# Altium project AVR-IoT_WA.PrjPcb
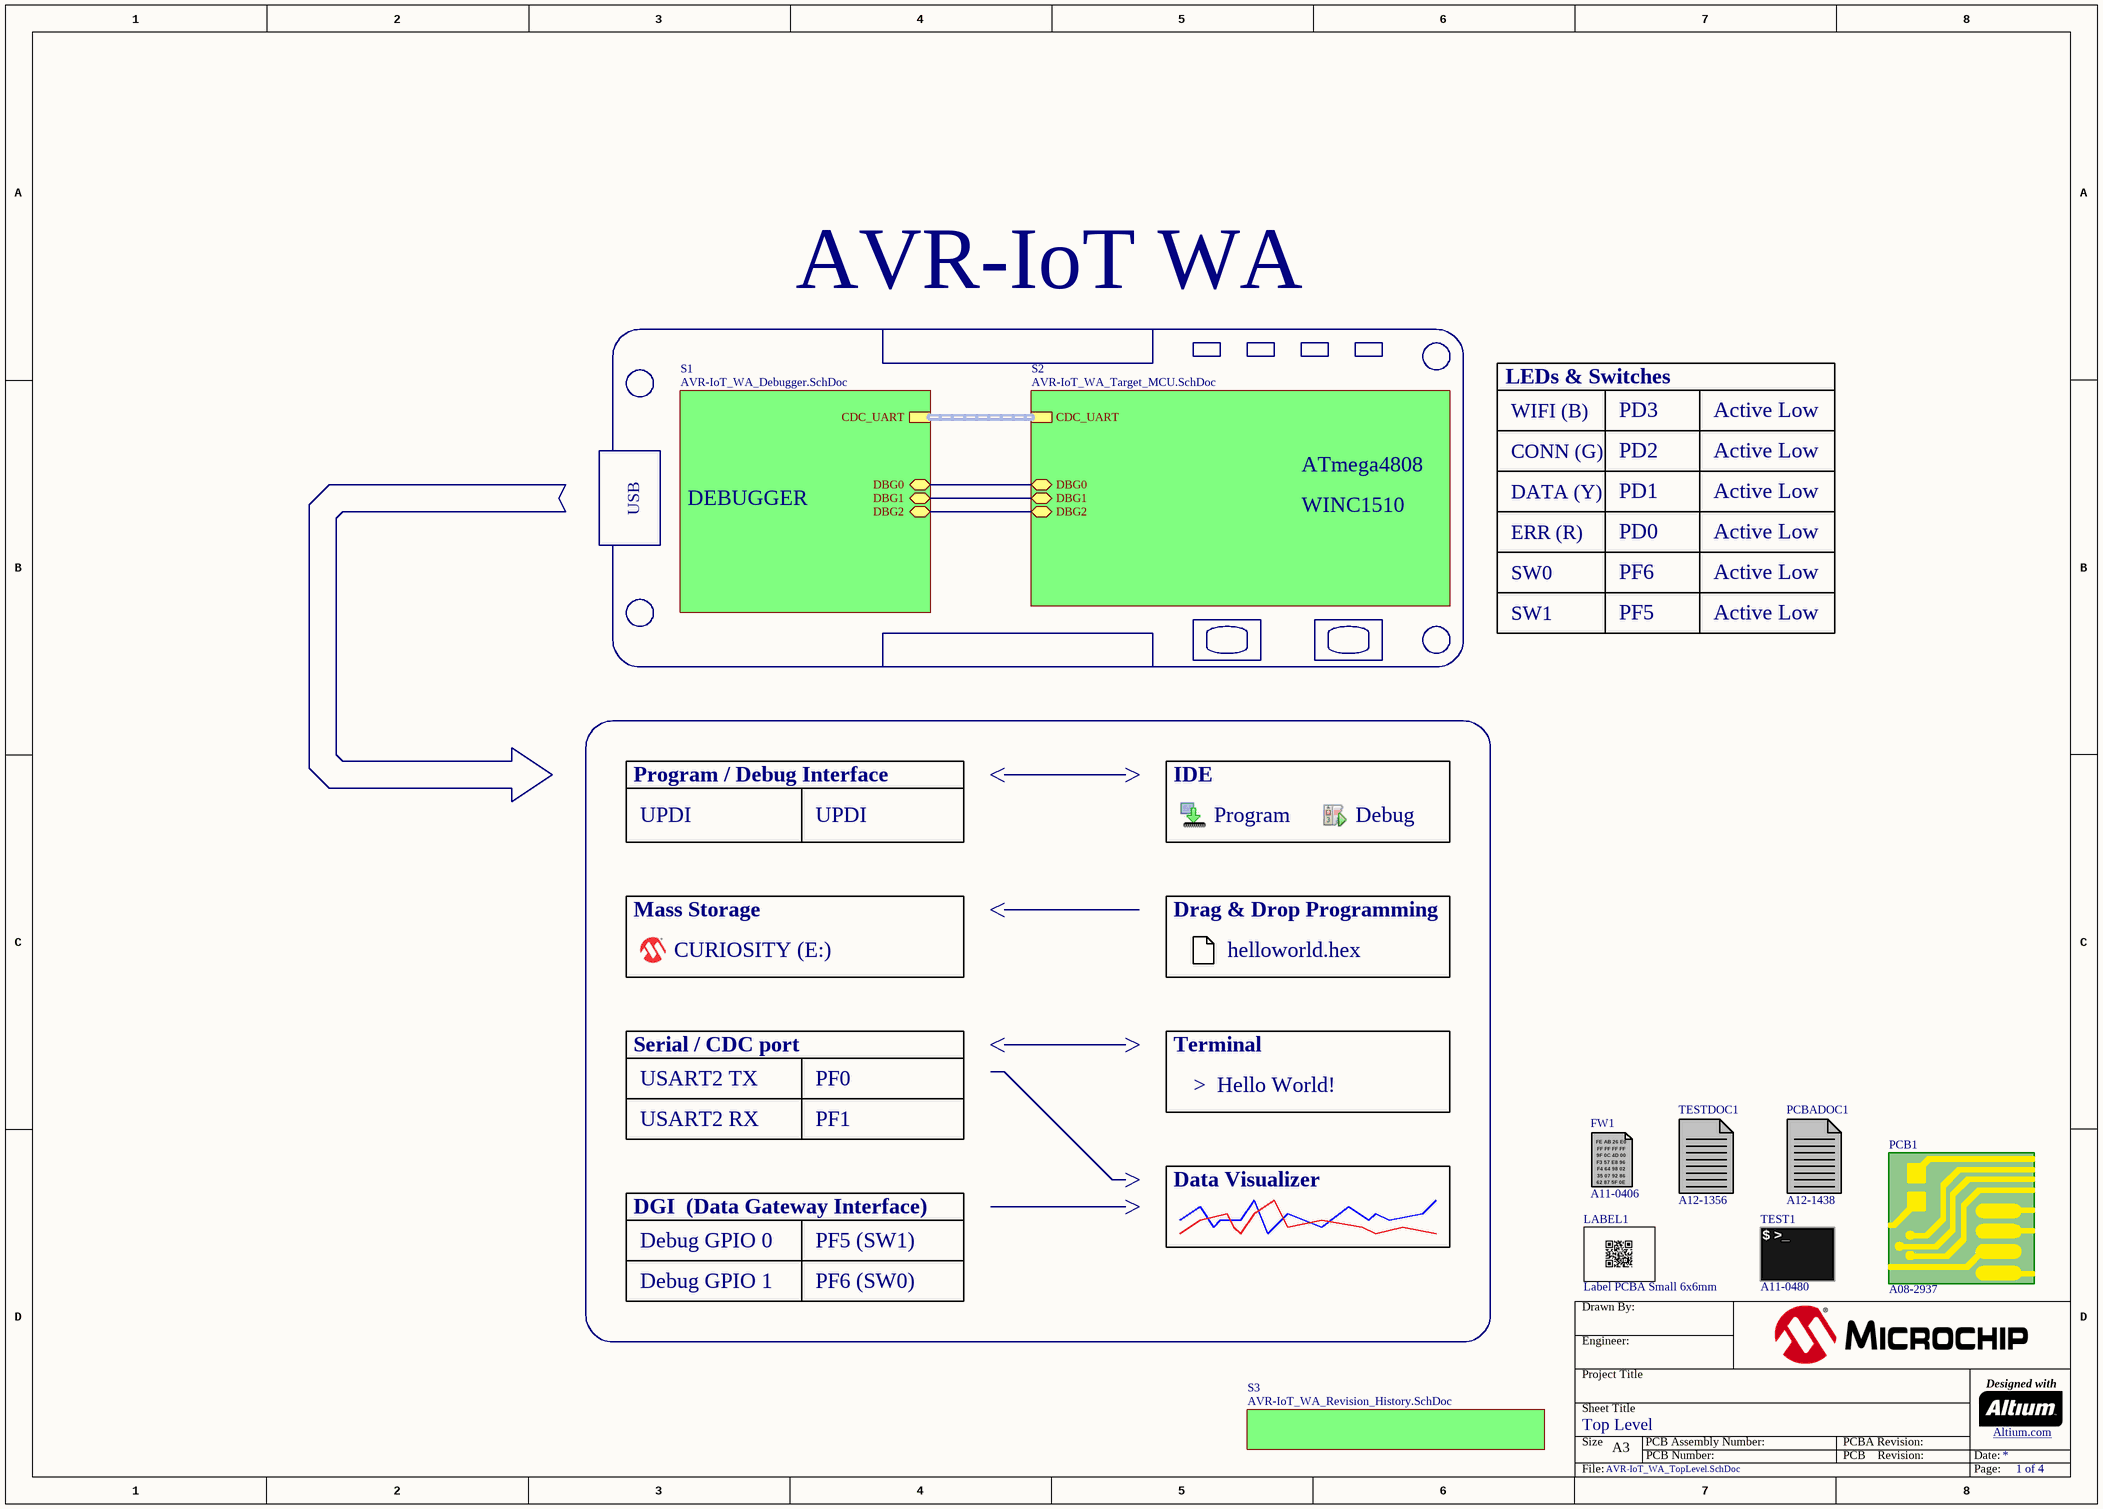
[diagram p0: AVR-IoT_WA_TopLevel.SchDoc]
Target_Name: ATmega4808; Project_Title: AVR-IoT WA; Project_Engineer: TF; Project_Drawn_By: TF; PCB_rev: 5; PCBA_rev: 1; Organization_1: Microchip Norway; AN_PCBA: A09-3349; AN_PCB: A08-2937; Address_3: Norway; Address_2: 7069 Trondheim; Address_1: Brøsetvegen 164
4 sheets, 86 parts. Net scope: hierarchical (ports join the sheet entries above them; power ports are global).
Board file: AVR-IoT_WA.PcbDoc
Sheets:
  AVR-IoT_WA_TopLevel.SchDoc
    S2 = AVR-IoT_WA_Target_MCU.SchDoc
    S1 = AVR-IoT_WA_Debugger.SchDoc
    S3 = AVR-IoT_WA_Revision_History.SchDoc

## Sheet AVR-IoT_WA_TopLevel.SchDoc: Top Level
size A3; Organization: Microchip Norway; Address1: Brøsetvegen 164; Address2: 7069 Trondheim; Address3: Norway; DocumentNumber: A09-3349; Revision: 1; SheetNumber: 1; SheetTotal: 4; DrawnBy: TF; Engineer: TF; PageSetup: Record=PageOptions¦CenterHorizontal=True¦CenterVertical=True¦PrintScale=1.01¦XCorrection=1.00¦YCorrection=1.00¦PrintKind=1¦BorderSize=5000000¦LeftOffset=0¦BottomOffset=0¦Orientation=2¦PaperLength=1000¦PaperWidth=1000¦Scale=100¦PaperSource=7¦PrintQuality=-4¦MediaType=1¦DitherType=10¦PaperKind=A3 (297 x 420 mm)¦PrintScaleMode=1; ProjectTitle: AVR-IoT WA; PCBNumber: A08-2937; PCBRevision: 5

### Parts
FW1  AN: A11-0406  (mechanical)
LABEL1  value Label PCBA Small 6x6mm  [AP9-00049]
PCB1  AN: A08-2937  (mechanical)
PCBADOC1  AN: A12-1438  (mechanical)
TEST1  AN: A11-0480  (mechanical)
TESTDOC1  AN: A12-1356  (hidden comment: Use test fixture A13-0177)  (mechanical)

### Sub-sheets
S1 = AVR-IoT_WA_Debugger.SchDoc: CDC_UART (harness UART), DBG2 (bidir), DBG1 (bidir), DBG0 (bidir)
S2 = AVR-IoT_WA_Target_MCU.SchDoc: DBG0 (bidir), CDC_UART (harness UART), DBG1 (bidir), DBG2 (bidir)
S3 = AVR-IoT_WA_Revision_History.SchDoc: no entries

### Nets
PF5_SW1_DGI: sheet S2/DBG2, sheet S1/DBG2
PF6_SW0_DGI: sheet S2/DBG1, sheet S1/DBG1
UPDI: sheet S2/DBG0, sheet S1/DBG0

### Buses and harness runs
harness sheet S1/CDC_UART = sheet S2/CDC_UART

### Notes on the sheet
- LEDs & Switches
- WIFI (B)
- PD3
- Active Low
- USB
- DEBUGGER
- WINC1510
- CONN (G)
- DATA (Y)
- PD2
- PD1
- SW0
- ERR (R)
- PF6
- PD0
- SW1
- PF5
- Program / Debug Interface
- IDE
- UPDI
- Program
- Debug
- Mass Storage
- Drag & Drop Programming
- CURIOSITY (E:)
- helloworld.hex
- Serial / CDC port
- Terminal
- USART2 TX
- USART2 RX
- PF1
- PF0
- >  Hello World!
- Data Visualizer
- DGI  (Data Gateway Interface)
- Debug GPIO 0
- PF5 (SW1)
- Debug GPIO 1
- PF6 (SW0)

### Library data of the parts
FW1 = A11-0406: nEDBG firmware; PartGroup: Software,Firmware,Tools; Value: debugger firmware
LABEL1 = A09-0612: PCBA identification label PP Top White Gloss; PartGroup: Mechanical devices,Packaging materials,Printed Labels,PCBA; Manufacturer: ACT Logimark AS; MPN: 505462
PCB1 = A08-2937: AVR-IoT Wx PCB documentation; PartGroup: Mechanical devices,Printed circuit boards
PCBADOC1 = A12-1438: AVR-IoT WA PCBA documentation; PartGroup: Documentation,PCBA Documents,Atmel; Value: A09-3349 AVR-IoT WA PCBA documentation
TEST1 = A11-0480: Fixture test for AVR-IoT WA test; PartGroup: Software,Test software,Starter Kit
TESTDOC1 = A12-1356: AVR-IoT Wx Test Instructions; PartGroup: Documentation,Procedures,Test Instructions

## Sheet AVR-IoT_WA_Target_MCU.SchDoc: Target MCU
size A3; Organization: Microchip Norway; Address1: Brøsetvegen 164; Address2: 7069 Trondheim; Address3: Norway; DocumentNumber: A09-3349; Revision: 1; SheetNumber: 2; SheetTotal: 4; DrawnBy: TF; Engineer: TF; PageSetup: Record=PageOptions¦CenterHorizontal=True¦CenterVertical=True¦PrintScale=1.01¦XCorrection=1.00¦YCorrection=1.00¦PrintKind=1¦BorderSize=5000000¦LeftOffset=0¦BottomOffset=0¦Orientation=2¦PaperLength=1000¦PaperWidth=1000¦Scale=100¦PaperSource=7¦PrintQuality=-4¦MediaType=1¦DitherType=10¦PaperKind=A3 (297 x 420 mm)¦PrintScaleMode=1; ProjectTitle: AVR-IoT WA; PCBNumber: A08-2937; PCBRevision: 5
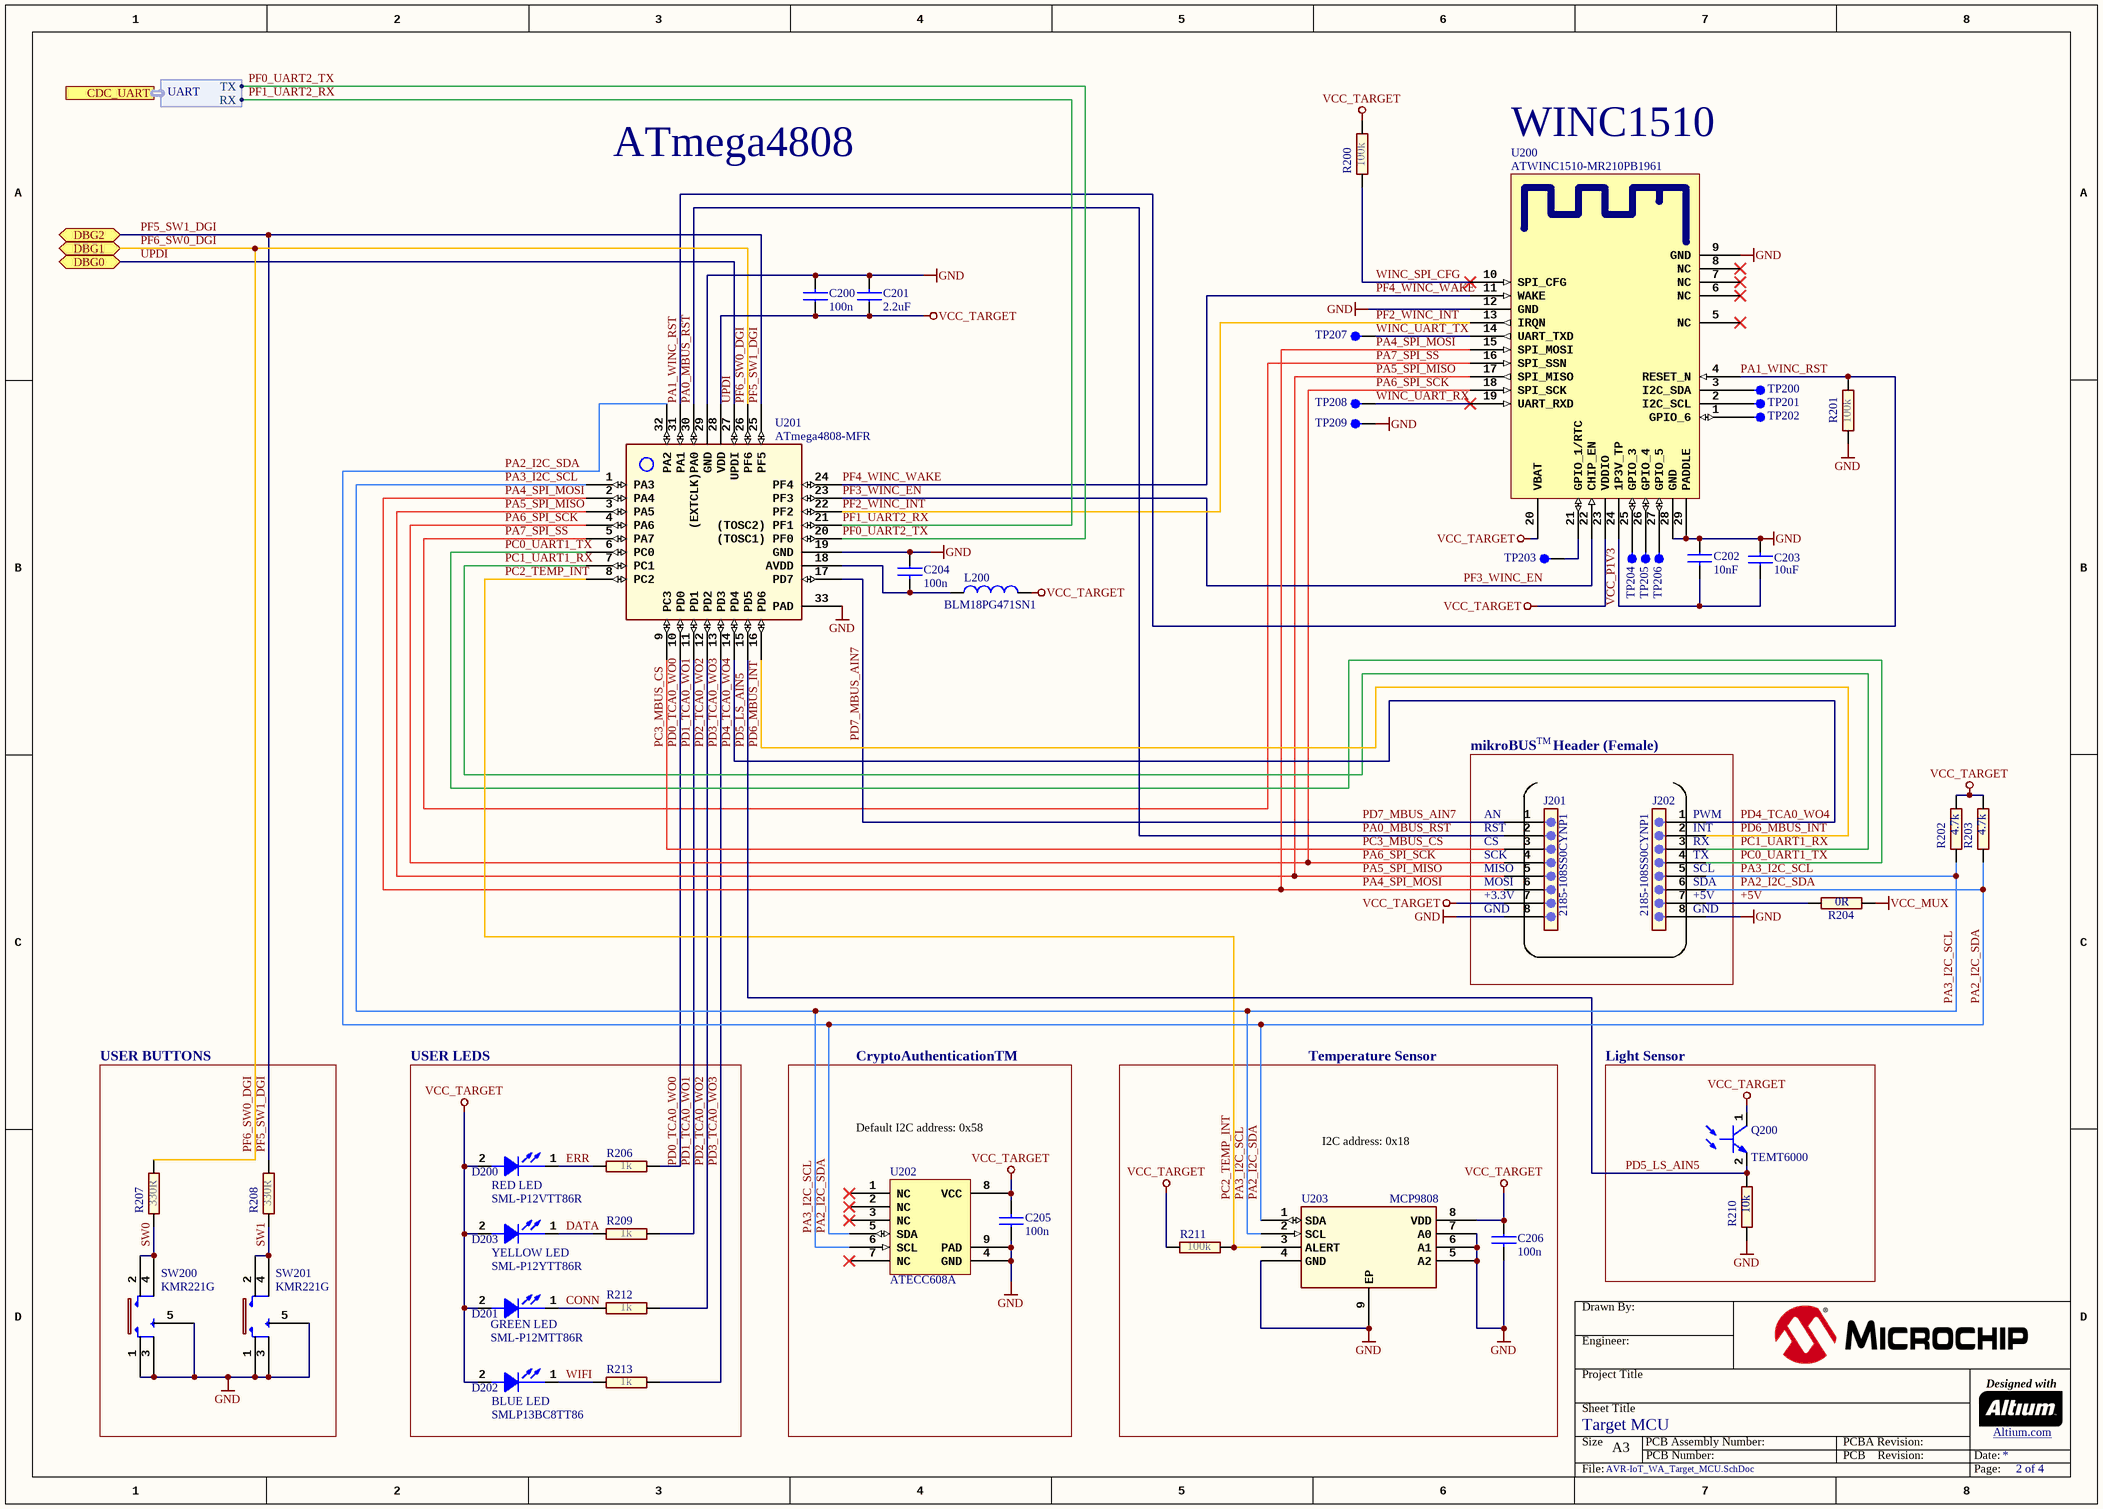
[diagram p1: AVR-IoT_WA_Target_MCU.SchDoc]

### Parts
C200  value 100n  [AP1-00053]
C201  value 2.2uF  [AP1-00053]
C202  value 10nF  [AP1-00053]
C203  value 10uF  [AP1-00053]
C204  value 100n  [AP1-00053]
C205  value 100n  [AP1-00053]
C206  value 100n  [AP1-00053]
D200  value RED LED  MPN: SML-P12VTT86R  [AP4-00160]
D201  value GREEN LED  MPN: SML-P12MTT86R  [AP4-00160]
D202  value BLUE LED  MPN: SMLP13BC8TT86  [AP4-00160]
D203  value YELLOW LED  MPN: SML-P12YTT86R  [AP4-00160]
J201  MPN: 2185-108SS0CYNP1  [AP8-01081]
J202  MPN: 2185-108SS0CYNP1  [AP8-01081]
L200  value BLM18PG471SN1  [AP3-00005]
Q200  value TEMT6000  [AP9-00011]
R200  value 100k  [AP2-00011]
R201  value 100k  [AP2-00011]
R202  value 4.7k  [AP2-00011]
R203  value 4.7k  [AP2-00011]
R204  value 0R  [AP2-00000]
R206  value 1k  [AP2-00011]
R207  value 330R  [AP2-00011]
R208  value 330R  [AP2-00011]
R209  value 1k  [AP2-00011]
R210  value 10k  [AP2-00011]
R211  value 100k  [AP2-00011]
R212  value 1k  [AP2-00011]
R213  value 1k  [AP2-00011]
SW200  value KMR221G  [AP8-00274]
SW201  value KMR221G  [AP8-00274]
TP200  (no value)  [AP8-01149]  (no BOM)
TP201  (no value)  [AP8-01149]  (no BOM)
TP202  (no value)  [AP8-01149]  (no BOM)
TP203  (no value)  [AP8-01149]  (no BOM)
TP204  (no value)  [AP8-01149]  (no BOM)
TP205  (no value)  [AP8-01149]  (no BOM)
TP206  (no value)  [AP8-01149]  (no BOM)
TP207  (no value)  [AP8-01149]  (no BOM)
TP208  (no value)  [AP8-01149]  (no BOM)
TP209  (no value)  [AP8-01149]  (no BOM)
U200  value ATWINC1510-MR210PB1961  [AP9-00127]  (hidden comment: Firmware version 19.6.1)
U201  value ATmega4808-MFR  [AP6-00418]
U202  (no value)  [AP6-00409]
U203  value MCP9808  [AP6-00519]

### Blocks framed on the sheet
USER BUTTONS: R207 R208 SW200 SW201
USER LEDS: D200-D203 R206 R209 R212 R213
CryptoAuthenticationTM: C205 U202
Temperature Sensor: C206 R211 U203
Light Sensor: Q200 R210

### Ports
CDC_UART (harness UART), DBG0 (bidir), DBG1 (bidir), DBG2 (bidir)

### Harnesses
UART: TX, RX

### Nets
GND: C200.2 C201.2 C202.1 C203.2 C204.1 C205.1 C206.2 J201.8 J202.8 R201.2 R210.2 SW200.1 SW200.3 SW200.5(GND) SW201.1 SW201.3 SW201.5(GND) TP209.1 U200.9(GND) U200.12(GND) U200.28(GND) U200.29(PADDLE) U201.19(GND) U201.29(GND) U201.33(PAD) U202.4(GND) U202.9(PAD) U203.4(GND) U203.5(A2) U203.6(A1) U203.7(A0) U203.9(EP)
VCC_MUX: R204.2
VCC_TARGET: C200.1 C201.1 C205.2 C206.1 D200.2(ANODE) D201.2(ANODE) D202.2(ANODE) D203.2(ANODE) J201.7 L200.2 Q200.1(C) R200.2 R202.1 R203.2 R211.1 U200.20(VBAT) U200.23(VDDIO) U201.28(VDD) U202.8(VCC) U203.8(VDD)
+5V: J202.7 R204.1
CONN: D201.1(CATHODE) R212.2
DATA: D203.1(CATHODE) R209.2
ERR: D200.1(CATHODE) R206.2
PA0_MBUS_RST: J201.2 U201.30((EXTCLK)PA0)
PA1_WINC_RST: R201.1 U200.4(RESET_N) U201.31(PA1)
PA2_I2C_SDA: J202.6 R203.1 U201.32(PA2) U202.5(SDA) U203.1(SDA)
PA3_I2C_SCL: J202.5 R202.2 U201.1(PA3) U202.6(SCL) U203.2(SCL)
PA4_SPI_MOSI: J201.6 U200.15(SPI_MOSI) U201.2(PA4)
PA5_SPI_MISO: J201.5 U200.17(SPI_MISO) U201.3(PA5)
PA6_SPI_SCK: J201.4 U200.18(SPI_SCK) U201.4(PA6)
PA7_SPI_SS: U200.16(SPI_SSN) U201.5(PA7)
PC0_UART1_TX: J202.4 U201.6(PC0)
PC1_UART1_RX: J202.3 U201.7(PC1)
PC2_TEMP_INT: R211.2 U201.8(PC2) U203.3(ALERT)
PC3_MBUS_CS: J201.3 U201.9(PC3)
PD0_TCA0_WO0: R206.1 U201.10(PD0)
PD1_TCA0_WO1: R209.1 U201.11(PD1)
PD2_TCA0_WO2: R212.1 U201.12(PD2)
PD3_TCA0_WO3: R213.1 U201.13(PD3)
PD4_TCA0_WO4: J202.1 U201.14(PD4)
PD5_LS_AIN5: Q200.2(E) R210.1 U201.15(PD5)
PD6_MBUS_INT: J202.2 U201.16(PD6)
PD7_MBUS_AIN7: J201.1 U201.17(PD7)
PF0_UART2_TX: U201.20((TOSC1)_PF0) ; port CDC_UART.TX
PF1_UART2_RX: U201.21((TOSC2)_PF1) ; port CDC_UART.RX
PF2_WINC_INT: U200.13(IRQN) U201.22(PF2)
PF3_WINC_EN: U200.22(CHIP_EN) U201.23(PF3)
PF4_WINC_WAKE: U200.11(WAKE) U201.24(PF4)
PF5_SW1_DGI: R208.1 U201.25(PF5) ; port DBG2
PF6_SW0_DGI: R207.1 U201.26(PF6) ; port DBG1
SW0: R207.2 SW200.2 SW200.4
SW1: R208.2 SW201.2 SW201.4
UPDI: U201.27(UPDI) ; port DBG0
VCC_P1V3: C202.2 C203.1 U200.24(1P3V_TP)
WIFI: D202.1(CATHODE) R213.2
WINC_SPI_CFG: R200.1 U200.10(SPI_CFG)
WINC_UART_RX: TP208.1 U200.19(UART_RXD)
WINC_UART_TX: TP207.1 U200.14(UART_TXD)
NetC204_2: C204.2 L200.1 U201.18(AVDD)
NetTP200_1: TP200.1 U200.3(I2C_SDA)
NetTP201_1: TP201.1 U200.2(I2C_SCL)
NetTP202_1: TP202.1 U200.1(GPIO_6)
NetTP203_1: TP203.1 U200.21(GPIO_1/RTC)
NetTP204_1: TP204.1 U200.25(GPIO_3)
NetTP205_1: TP205.1 U200.26(GPIO_4)
NetTP206_1: TP206.1 U200.27(GPIO_5)

Not connected (* = marked no-connect by the designer): Q200 3; U200 5(NC)* 6(NC)* 7(NC)* 8(NC)*; U202 1(NC)* 2(NC)* 3(NC)* 7(NC)*

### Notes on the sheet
- WINC1510
- mikroBUS
- TM
- Header (Female)
- (near J201) AN
- (near J201) RST
- (near J201) CS
- (near J201) SCK
- (near J202) PWM
- (near J202) INT
- (near J202) RX
- (near J202) TX
- (near J201) MISO
- (near J201) MOSI
- (near J201) +3.3V
- (near J201) GND
- (near J202) SCL
- (near J202) SDA
- (near J202) +5V
- (near J202) GND
- Default I2C address: 0x58
- I2C address: 0x18
- (near U202) ATECC608A

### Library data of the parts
C200 C204-C206 = A01-0246: Ceramic capacitor, SMD 0402, X7R, 16V, +/-10%; Manufacturer: Kemet; MPN: C0402C104K4RACTU; PartGroup: Capacitors,Ceramic,SMD 0402; TemperatureRange: -55 - +125 deg C
C201 = A01-0493: CAP CER 2.2UF 10V 10% X5R 0402; PartGroup: Capacitors,Ceramic,SMD 0402; Manufacturer: tdk; MPN: C1005X5R1A225K; Tolerance: +/-10%; TemperatureRange: -55 to 85C
C202 = A01-0636: Ceramic capacitor, SMD 0402, X7R, 25V, 10%; PartGroup: Capacitors,Ceramic,SMD 0402; Manufacturer: Murata; MPN: GRM155R71E103KA01D; TemperatureRange: -55 to +125deg C
C203 = A01-0778: Ceramic capacitor, SMD 0402, X5R, 6.3V, 20%; PartGroup: Capacitors,Ceramic,SMD 0402; Manufacturer: Murata; MPN: GRM155R60J106ME15; Tolerance: +/-20%; TemperatureRange: -55 to 85 Deg.C
D200 = A10-0220: LED, SMD 0402, Red, Wave length=630nm, 2.1mcd @ (1mA, 1.7Vf)rohm; PartGroup: Opto,LEDs,SMD; TemperatureRange: -40 to +85
D201 = A10-0213: LED, SMD 0402, Green, Wave length=569nm, 2.1mcd @ (1mA, 1.9Vf)rohm; PartGroup: Opto,LEDs,SMD; TemperatureRange: -40 to +85
D202 = A10-0219: LED, SMD 0402, Blue, Wave length=470nm, 25mcd @ (5mA, 2.9Vf)rohm; PartGroup: Opto,LEDs,SMD; TemperatureRange: -40Â°C to +85Â°C
D203 = A10-0215: LED, SMD 0402, Yellow, Wave length=586nm, 7.6mcd @ (1mA, 1.9Vf); PartGroup: Opto,LEDs,SMD; Manufacturer: ROHM; TemperatureRange: -40 to +85
J201 J202 = A08-2791: 1x8 receptacle pin header, 2.54mm pitch THM, PIP; PartGroup: Mechanical devices,Connectors,Pin header receptacle; Manufacturer: WCON; Value: 2185-108SS0CYNP1
L200 = A03-0035: SMD RF inductor 0603. Z=470Ohm (@100MHz), Max R(dc)=0.20Ohm, Max current=1A; PartGroup: Inductors,EMI; Manufacturer: Murata; TemperatureRange: -55
Q200 = A10-0025: light sensor; PartGroup: Opto; Manufacturer: vishay; MPN: TEMT6000X01
R200 R201 R211 = A02-0260: Thick film resistor, SMD 0402, 1/16W, 1%; PartGroup: Resistors,SMD,0402 1%; Manufacturer: ASJ Holdings; MPN: CR10-1003-FK; TemperatureRange: -55ï¿½ to +125ï¿½C
R202 R203 = A02-1016: Thick film resistror, SMD 0402, 1/16W, 1%; PartGroup: Resistors,SMD,0402 1%; Manufacturer: Yageo; MPN: RC0402FR-074K7L; TemperatureRange: -55 to +155 deg C
R204 = A02-0163: RES 0.0 OHM 1/16W 0402 SMD; PartGroup: Resistors,SMD,0402 1%; Manufacturer: (n/a); MPN: RMCF0402ZT0R00; Tolerance: 1 %; TemperatureRange: -55 - +125 deg C
R206 R209 R212 R213 = A02-0212: Thick film resistor, SMD 0402, 1/16W, 1%; PartGroup: Resistors,SMD,0402 1%; Manufacturer: ASJ Holdings; MPN: CR10-1001-FK; TemperatureRange: -55 - +125 deg C
R207 R208 = A02-0882: Thick film resistor, SMD 0402, 1/16W, 1%; Manufacturer: Yageo; MPN: RC0402FR-07330RL; PartGroup: Resistors,SMD,0402 1%; TemperatureRange: -55 to +155 deg C
R210 = A02-0835: Thick film resistror, SMD 0402, 1/16W, 1%; PartGroup: Resistors,SMD,0402 1%; Manufacturer: Yageo; MPN: RC0402FR-0710KL; TemperatureRange: â€“55 to +155 deg C
SW200 SW201 = A08-0420: Microminiature Tact Switch for SMT; PartGroup: Mechanical devices,Switches,SMD; Manufacturer: ITT Corporation
TP200-TP209 = A08-2933: SMD Single Testpad, 1mm, No-silk; PartGroup: Mechanical devices,Connectors,Test points
U200 = A06-1660: IEEE 802.11 b/g/n module, 8Mbit Flash Memory, with FEM, PCB Antenna, with Shield, with MAC, Firmware version 19.6.1; PartGroup: Integrated Circuits,Modules,Radio Module WiFi; Manufacturer: Microchip; TemperatureRange: -40Â°C to +85Â°C
U201 = A06-1639: Atmel 8-bit RISC MCU, 48K Flash, 32pin QFN; PartGroup: Integrated Circuits,MCU, MPU, DSP,AVR MCU; Manufacturer: Microchip; TemperatureRange: -40Â°C to +125Â°C
U202 = A06-1647: ATECC608A with an I2C Interface and a 8 Pin UDFN; Manufacturer: Microchip; MPN: ATECC608A-MAH1H-S; PartGroup: Integrated Circuits,Special function,Encryption; Value: ATECC608A I2C (Google Cloud)
U203 = A06-1645: Â±0.5Â°C Maximum Accuracy Digital Temperature Sensor, I2C/SMBus; PartGroup: Integrated Circuits,Sensors; Manufacturer: Microchip; MPN: MCP9808T-E/MC; TemperatureRange: -40Â°C to +125Â°C

## Sheet AVR-IoT_WA_Debugger.SchDoc: Debugger
size A3; Organization: Microchip Norway; Address1: Brøsetvegen 164; Address2: 7069 Trondheim; Address3: Norway; DocumentNumber: A09-3349; Revision: 1; SheetNumber: 3; SheetTotal: 4; DrawnBy: TF; Engineer: TF; PageSetup: Record=PageOptions¦CenterHorizontal=True¦CenterVertical=True¦PrintScale=1.01¦XCorrection=1.00¦YCorrection=1.00¦PrintKind=1¦BorderSize=5000000¦LeftOffset=0¦BottomOffset=0¦Orientation=2¦PaperLength=1000¦PaperWidth=1000¦Scale=100¦PaperSource=7¦PrintQuality=-4¦MediaType=1¦DitherType=10¦PaperKind=A3 (297 x 420 mm)¦PrintScaleMode=1; ProjectTitle: AVR-IoT WA; PCBNumber: A08-2937; PCBRevision: 5
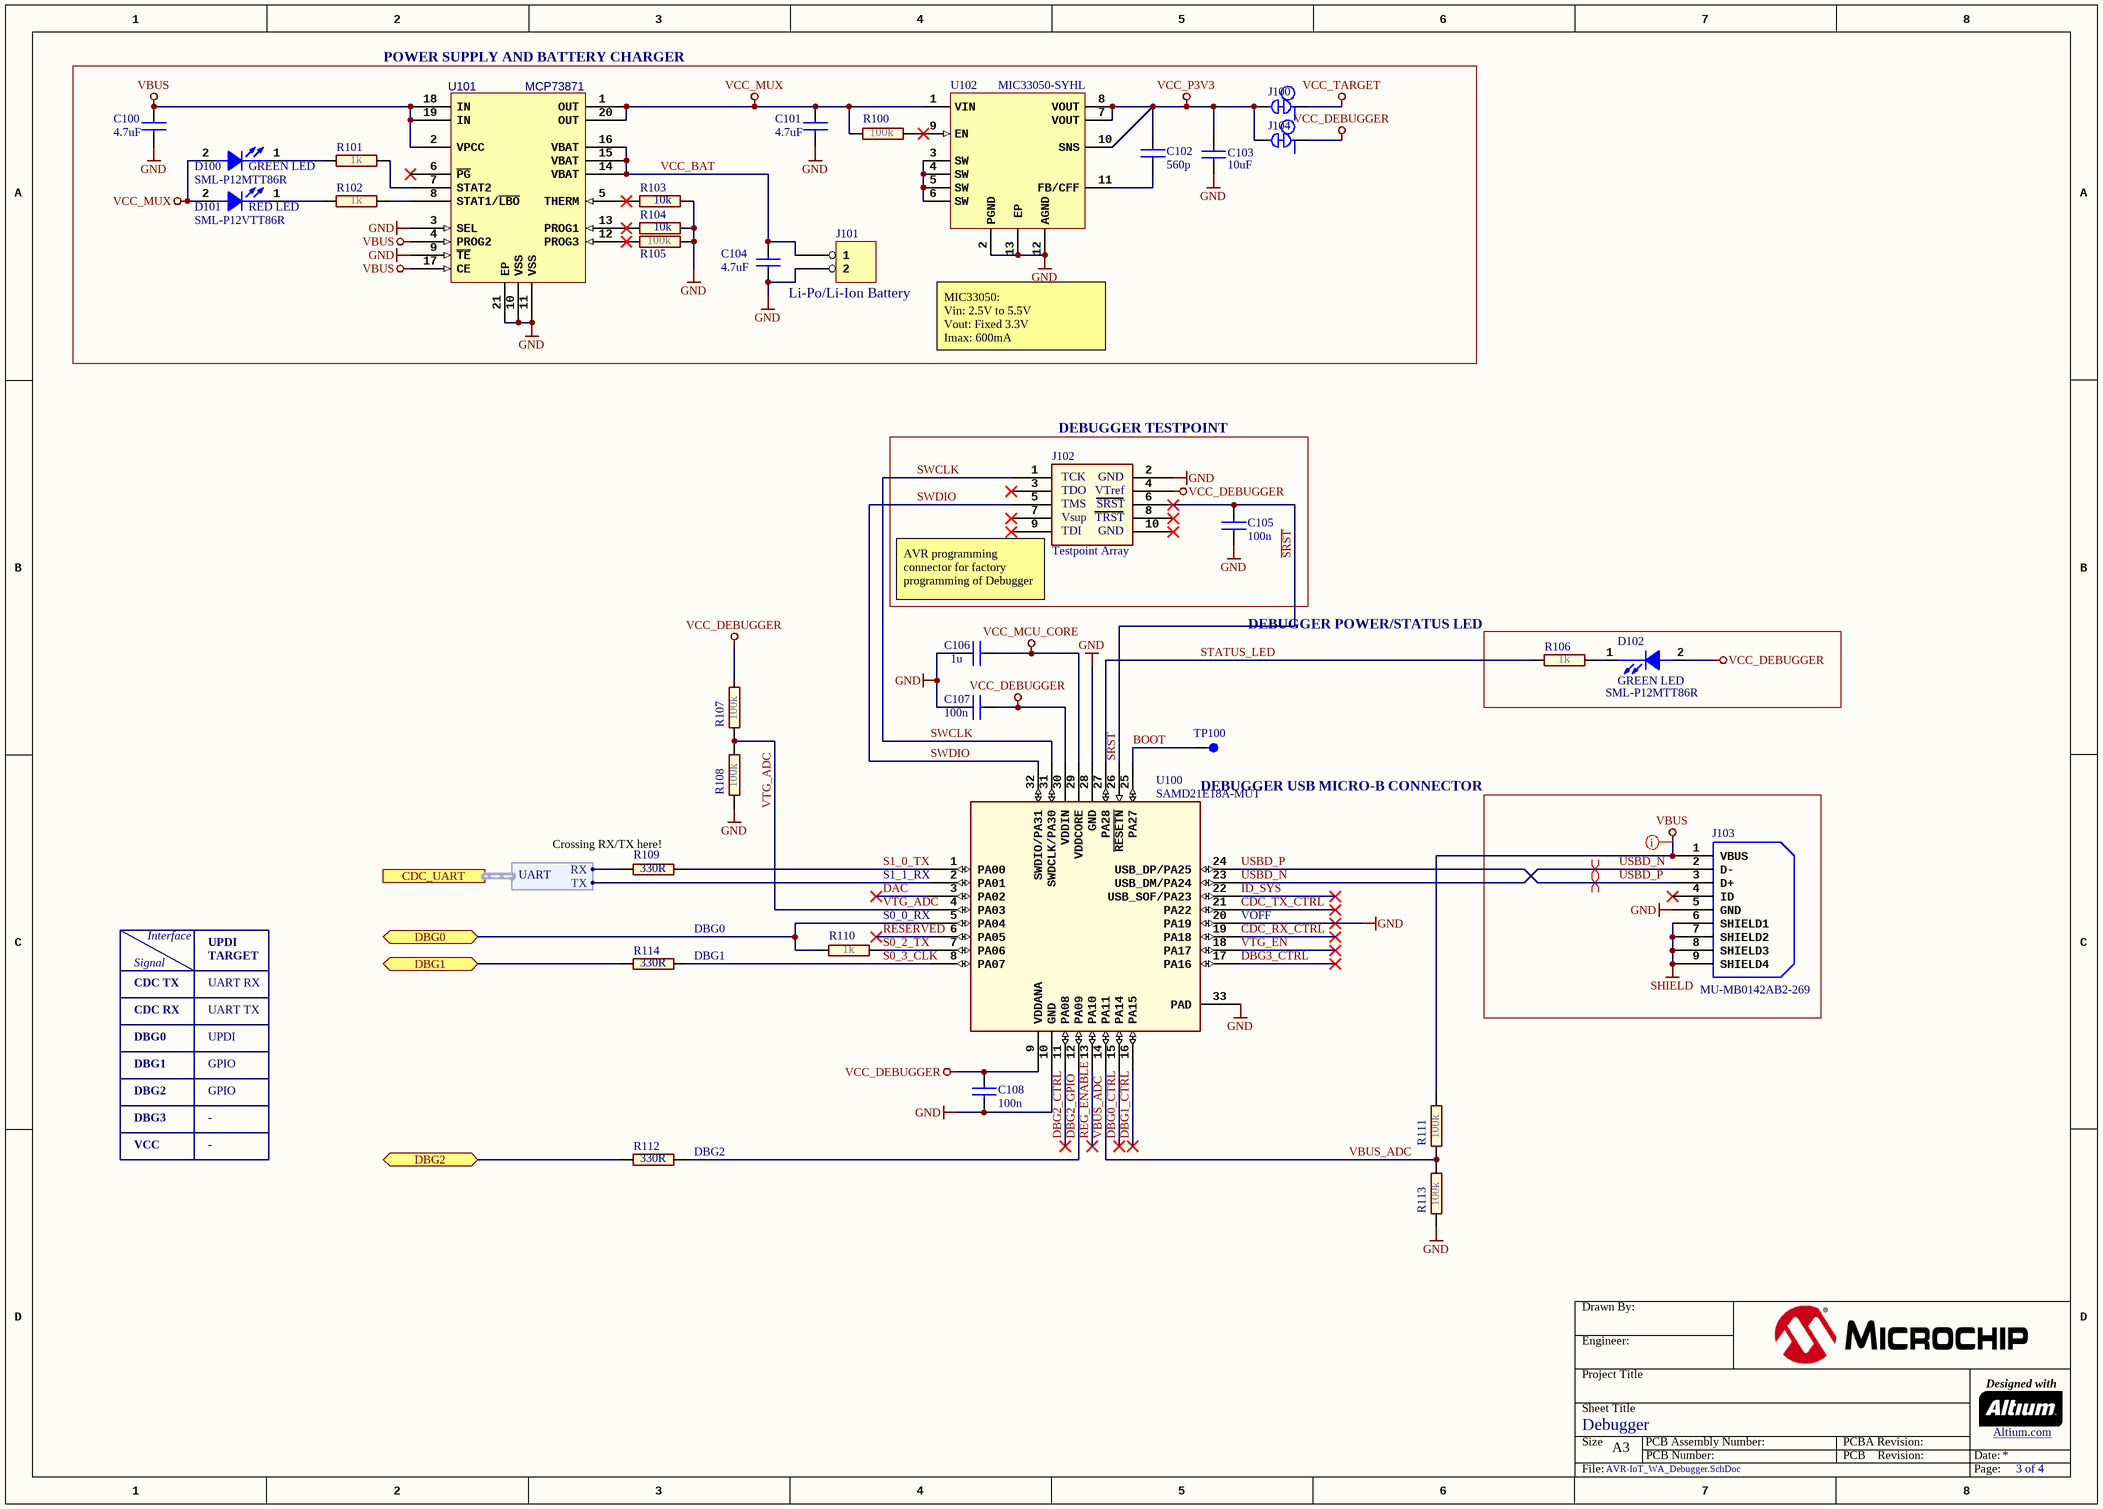
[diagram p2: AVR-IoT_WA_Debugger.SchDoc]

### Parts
C100  value 4.7uF  [AP1-00117]
C101  value 4.7uF  [AP1-00117]
C102  value 560p  [AP1-00053]
C103  value 10uF  [AP1-00053]
C104  value 4.7uF  [AP1-00117]
C105  value 100n  [AP1-00053]
C106  value 1u  [AP1-00053]
C107  value 100n  [AP1-00053]
C108  value 100n  [AP1-00053]
D100  value GREEN LED  MPN: SML-P12MTT86R  [AP4-00160]
D101  value RED LED  MPN: SML-P12VTT86R  [AP4-00160]
D102  value GREEN LED  MPN: SML-P12MTT86R  [AP4-00160]
J100  (no value)  [AP9-00044]  (net tie, no BOM)
J101  (no value)  [AP8-00831]
J102  value Testpoint Array  [AP8-00997]  (no BOM)
J103  value MU-MB0142AB2-269  [AP8-01099]
J104  (no value)  [AP9-00044]  (net tie, no BOM)
R100  value 100k  [AP2-00011]
R101  value 1k  [AP2-00011]
R102  value 1k  [AP2-00011]
R103  value 10k  [AP2-00011]
R104  value 10k  [AP2-00011]
R105  value 100k  [AP2-00011]
R106  value 1k  [AP2-00011]
R107  value 100k  [AP2-00011]
R108  value 100k  [AP2-00011]
R109  value 330R  [AP2-00011]
R110  value 1k  [AP2-00011]
R111  value 100k  [AP2-00011]
R112  value 330R  [AP2-00011]
R113  value 100k  [AP2-00011]
R114  value 330R  [AP2-00011]
TP100  PCB implemented component.  [AP8-00870]  (value not drawn)  (no BOM)
U100  value SAMD21E18A-MUT  [AP6-00418]  (hidden comment: QFN32)
U101  value MCP73871  [AP6-00165]
U102  value MIC33050-SYHL  [AP6-00528]

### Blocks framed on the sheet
DEBUGGER TESTPOINT: C105 J102
DEBUGGER POWER/STATUS LED: D102 R106
DEBUGGER USB MICRO-B CONNECTOR: J103

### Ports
CDC_UART (harness UART), DBG0 (bidir), DBG1 (bidir), DBG2 (bidir)

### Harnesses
UART: RX, TX

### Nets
GND: C100.2 C101.2 C103.1 C104.1 C105.1 C106.1 C107.1 C108.2 J101.2 J102.2 J103.5(GND) R103.2 R104.2 R105.2 R108.1 R113.2 U100.10(GND) U100.20(PA19) U100.28(GND) U100.33(PAD) U101.3(SEL) U101.9(~{TE}) U101.10(VSS) U101.11(VSS) U101.21(EP) U102.2(PGND) U102.12(AGND) U102.13(EP)
SHIELD: J103.6(SHIELD1) J103.7(SHIELD2) J103.8(SHIELD3) J103.9(SHIELD4)
VBUS: C100.1 J103.1(VBUS) R111.2 U101.2(VPCC) U101.4(PROG2) U101.17(CE) U101.18(IN) U101.19(IN)
VCC_DEBUGGER: C107.2 C108.1 D102.2(ANODE) J102.4 J104.1 R107.2 U100.9(VDDANA) U100.30(VDDIN)
VCC_MCU_CORE: C106.2 U100.29(VDDCORE)
VCC_MUX: C101.1 D100.2(ANODE) D101.2(ANODE) R100.1 U101.1(OUT) U101.20(OUT) U102.1(VIN)
VCC_P3V3: C102.1 C103.2 J100.2 J104.2 U102.7(VOUT) U102.8(VOUT) U102.10(SNS)
VCC_TARGET: J100.1
BOOT: TP100.1 U100.25(PA27)
CDC_RX_CTRL: U100.19(PA18)
CDC_TX_CTRL: U100.21(PA22)
DAC: U100.3(PA02)
DBG0_CTRL: U100.15(PA14)
DBG1_CTRL: U100.16(PA15)
DBG2_CTRL: U100.11(PA08)
DBG2_GPIO: R112.1 U100.12(PA09)
DBG3_CTRL: U100.17(PA16)
ID_SYS: U100.22(USB_SOF/PA23)
PF0_UART2_TX: U100.2(PA01) ; port CDC_UART.TX
PF1_UART2_RX: R109.1 ; port CDC_UART.RX
PF5_SW1_DGI: R112.2 ; port DBG2
PF6_SW0_DGI: R114.2 ; port DBG1
REG_ENABLE: U100.13(PA10)
RESERVED: U100.6(PA05)
S0_2_TX: R110.2 U100.7(PA06)
S0_3_CLK: R114.1 U100.8(PA07)
S1_0_TX: R109.2 U100.1(PA00)
~{SRST}: C105.2 J102.6 U100.26(~{RESETN})
STATUS_LED: R106.2 U100.27(PA28)
SWCLK: J102.1 U100.31(SWDCLK/PA30)
SWDIO: J102.5 U100.32(SWDIO/PA31)
UPDI: R110.1 U100.5(PA04) ; port DBG0
USBD_N: J103.2(D-) U100.23(USB_DM/PA24)
USBD_P: J103.3(D+) U100.24(USB_DP/PA25)
VBUS_ADC: R111.1 R113.1 U100.14(PA11)
VCC_BAT: C104.2 J101.1 U101.14(VBAT) U101.15(VBAT) U101.16(VBAT)
VTG_ADC: R107.1 R108.2 U100.4(PA03)
VTG_EN: U100.18(PA17)
NetC102_2: C102.2 U102.11(FB/CFF)
NetD100_1: D100.1(CATHODE) R101.2
NetD101_1: D101.1(CATHODE) R102.2
NetD102_1: D102.1(CATHODE) R106.1
NetR100_2: R100.2 U102.9(EN)
NetR101_1: R101.1 U101.7(STAT2)
NetR102_1: R102.1 U101.8(STAT1/~{LBO})
NetR103_1: R103.1 U101.5(THERM)
NetR104_1: R104.1 U101.13(PROG1)
NetR105_1: R105.1 U101.12(PROG3)
NetU102_3: U102.3(SW) U102.4(SW) U102.5(SW) U102.6(SW)

Not connected (* = marked no-connect by the designer): J102 3* 7* 8* 9* 10*; J103 4(ID)*; U101 6(~{PG})*

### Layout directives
differential pair: USBD_N, USBD_P
net class Power: VBUS

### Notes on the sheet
- POWER SUPPLY AND BATTERY CHARGER
- Li-Po/Li-Ion Battery
- MIC33050:
  Vin: 2.5V to 5.5V
  Vout: Fixed 3.3V
  Imax: 600mA
- (near J102) AVR programming connector for factory programming of Debugger
- (near R109) Crossing RX/TX here!
- S1_1_RX
- S0_0_RX
- (near U100) VOFF
- Signal
- CDC TX
- Interface
- UPDI
- UART RX
- TARGET
- (near R114) DBG0
- (near R114) DBG1
- DBG0
- CDC RX
- UART TX
- DBG1
- DBG2
- DBG3
- GPIO
- -
- VCC
- (near R112) DBG2

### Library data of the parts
C100 C101 C104 = A01-0377: Ceramic capacitor, SMD 0603, X5R, 10V, 10% (de31036); PartGroup: Capacitors,Ceramic,SMD 0603; Manufacturer: WALSIN Technology Corporation; MPN: 0603X475K100CT; TemperatureRange: -55 - +85 deg C
C102 = A01-0035: Ceramic capacitor, SMD 0402, X7R, 50V, +/-10%; PartGroup: Capacitors,Ceramic,SMD 0402; TemperatureRange: -55 - +125 deg C
C103 = A01-0778: as C203 on sheet AVR-IoT_WA_Target_MCU
C105 C107 C108 = A01-0246: Ceramic capacitor, SMD 0402, X7R, 16V, +/-10%; PartGroup: Capacitors,Ceramic,SMD 0402; Manufacturer: Kemet; MPN: C0402C104K4RACTU; TemperatureRange: -55 - +125 deg C
C106 = A01-0286: Ceramic capacitor, SMD 0402, X5R, 6.3V, +/-10% (de26942); PartGroup: Capacitors,Ceramic,SMD 0402; Manufacturer: Kemet; MPN: C0402C105K9PAC; TemperatureRange: -55 to 85 deg C
D100 D102 = A10-0213: as D201 on sheet AVR-IoT_WA_Target_MCU
D101 = A10-0220: as D200 on sheet AVR-IoT_WA_Target_MCU
J100 J104 = A09-0783: Default closed SMD strap, 0603 size; PartGroup: Mechanical devices,PCB implemented components; Value: SMD-STRAP_0603_CLOSED
J101 = A08-2071: Pin Header 1x2, 2mm THM, right entry, 100V AC/DC, 2A AC/DC (AWG #24)  (Element14:9491902); PartGroup: Mechanical devices,Connectors,Pin headers; Manufacturer: J.S.T. Mfg. Co. Ltd.; Value: S2B-PH-K-S; TemperatureRange: -25Â°C to +85Â°C
J102 = A08-2568: 10-pin Testpoint Array, 0.8mm Pad, 1.27mm Pitch; PartGroup: Mechanical devices,PCB implemented components,PCB plane connectors
J103 = A08-2839: USB micro AB, Surface mount signals and DIP shield; PartGroup: Mechanical devices,Connectors,USB; Manufacturer: Allen Creations Corp.; TemperatureRange: -30Â°C to +80Â°C
R100 R105 = A02-0260: as R200 on sheet AVR-IoT_WA_Target_MCU
R101 R102 R106 R110 = A02-0212: as R206 on sheet AVR-IoT_WA_Target_MCU
R103 R104 = A02-0835: as R210 on sheet AVR-IoT_WA_Target_MCU
R107 R108 R111 R113 = A02-0260: Thick film resistor, SMD 0402, 1/16W, 1%; Manufacturer: ASJ Holdings; MPN: CR10-1003-FK; PartGroup: Resistors,SMD,0402 1%; TemperatureRange: -55ï¿½ to +125ï¿½C
R109 R112 R114 = A02-0882: Thick film resistor, SMD 0402, 1/16W, 1%; PartGroup: Resistors,SMD,0402 1%; Manufacturer: Yageo; MPN: RC0402FR-07330RL; TemperatureRange: -55 to +155 deg C
TP100 = A08-2176: SMD Test point - 0.8mm; PartGroup: Mechanical devices,Connectors,Test points
U100 = A06-1205: 32-bit RISC MCU 32pin; PartGroup: Integrated Circuits,MCU, MPU, DSP,ARM MCU; Manufacturer: Microchip; MPN: ATSAMD21E18A-MUT; TemperatureRange: -40Â°C to +85Â°C
U101 = A06-1643: Load Sharing and Li-Ion/Li-Polymer Battery Charge Management Controller; Manufacturer: Microchip; PartGroup: Integrated Circuits,Regulators,Switched; MPN: MCP73871T-2CCI/ML; TemperatureRange: -40Â°C to  +85Â°C
U102 = A06-1644: 3.3V Fixed, 4MHz, 600mA, Buck regulator with internal inductor with HyperLight Load; PartGroup: Integrated Circuits,Regulators,Switched; Manufacturer: Microchip; MPN: MIC33050-SYHL-TR; TemperatureRange: -40C to +125C

## Sheet AVR-IoT_WA_Revision_History.SchDoc: Revision History
size A3; Organization: Microchip Norway; Address1: Brøsetvegen 164; Address2: 7069 Trondheim; Address3: Norway; DocumentNumber: A09-3349; Revision: 1; SheetNumber: 4; SheetTotal: 4; DrawnBy: TF; Engineer: TF; PageSetup: Record=PageOptions¦CenterHorizontal=True¦CenterVertical=True¦PrintScale=1.01¦XCorrection=1.00¦YCorrection=1.00¦PrintKind=1¦BorderSize=5000000¦LeftOffset=0¦BottomOffset=0¦Orientation=2¦PaperLength=1000¦PaperWidth=1000¦Scale=100¦PaperSource=7¦PrintQuality=-4¦MediaType=1¦DitherType=10¦PaperKind=A3 (297 x 420 mm)¦PrintScaleMode=1; ProjectTitle: AVR-IoT WA; PCBNumber: A08-2937; PCBRevision: 5
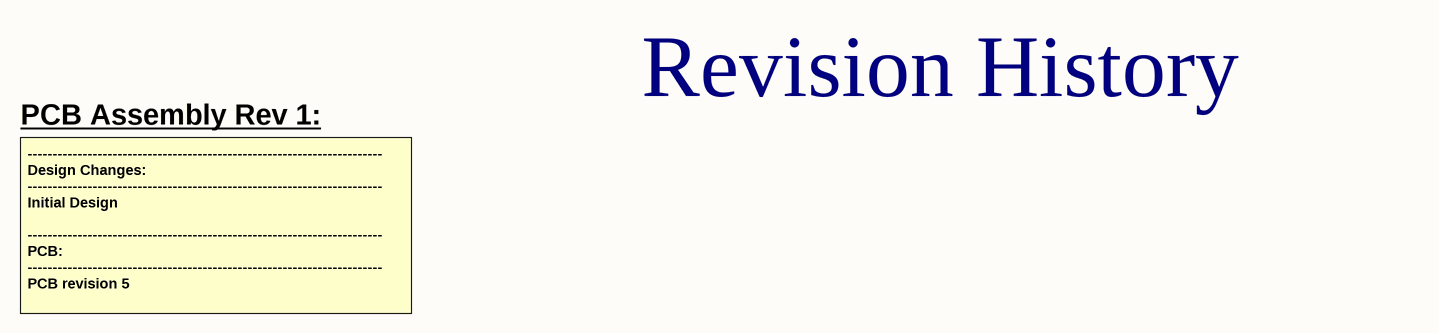
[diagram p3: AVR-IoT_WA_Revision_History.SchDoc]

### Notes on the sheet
- PCB Assembly Rev 1:
- Revision History
- -----------------------------------------------------------------------
  Design Changes:
  -----------------------------------------------------------------------
  Initial Design
  -----------------------------------------------------------------------
  PCB:
  -----------------------------------------------------------------------
  PCB revision 5

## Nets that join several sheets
GND: AVR-IoT_WA_Target_MCU (32 pins), AVR-IoT_WA_Debugger (28 pins)
VCC_MUX: AVR-IoT_WA_Target_MCU (R204.2), AVR-IoT_WA_Debugger (7 pins)
VCC_TARGET: AVR-IoT_WA_Target_MCU (20 pins), AVR-IoT_WA_Debugger (J100.1)
PF0_UART2_TX: AVR-IoT_WA_Target_MCU (U201.20), AVR-IoT_WA_Debugger (U100.2)
PF1_UART2_RX: AVR-IoT_WA_Target_MCU (U201.21), AVR-IoT_WA_Debugger (R109.1)
PF5_SW1_DGI: AVR-IoT_WA_Target_MCU (R208.1 U201.25), AVR-IoT_WA_Debugger (R112.2)
PF6_SW0_DGI: AVR-IoT_WA_Target_MCU (R207.1 U201.26), AVR-IoT_WA_Debugger (R114.2)
UPDI: AVR-IoT_WA_Target_MCU (U201.27), AVR-IoT_WA_Debugger (R110.1 U100.5)

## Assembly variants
Default Assembly: all parts fitted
